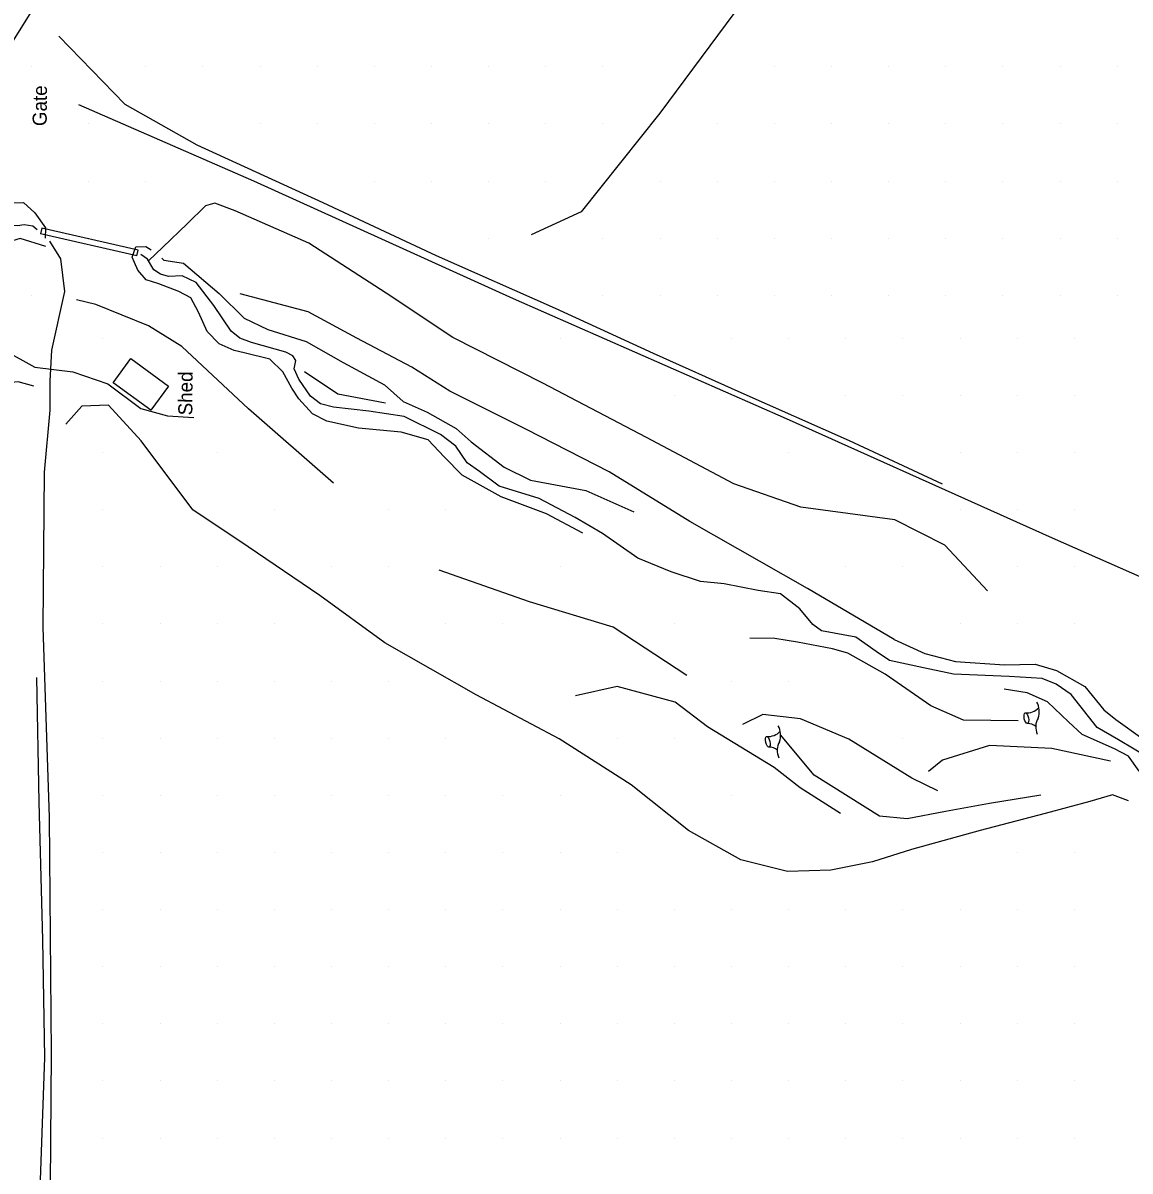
# Model space of a CAD drawing. Extents: x 19528164 to 19545171, y 7585743 to 7602745.
# Drawn here: x 19541782 to 19542169.5, y 7597363.5 to 7597765.3 of the extents above; entities that cross this region are included whole.
import ezdxf

# ---------------------------------------------------------------- set-up
doc = ezdxf.new("R2010")
doc.units = 0
for name, color, linetype in [('PhoBreakLine', 7, 'Continuous'), ('PhoBuilding', 7, 'Continuous'), ('PhoCulvert', 7, 'Continuous'), ('PhoDrainageArrow', 7, 'Continuous'), ('PhoEdgeBank', 7, 'Continuous'), ('PhoFence', 7, 'Continuous'), ('PhoISAEPoints', 7, 'Continuous'), ('PhoNotesDesign', 7, 'Continuous'), ('PhoSurveyLimits', 7, 'Continuous'), ('PhoVegetation', 7, 'Continuous'), ('SurBreakLine', 7, 'Continuous')]:
    doc.layers.add(name, color=color, linetype=linetype)

msp = doc.modelspace()

# ---------------------------------------------------------------- linework, layer by layer
at = {"layer": 'PhoBreakLine'}
for points in [[(19541794.59, 7597760.67), (19541817.6, 7597736.91), (19541842.87, 7597722.72), (19541886.98, 7597702.52), (19541926.62, 7597683.95), (19541968.3, 7597665.55), (19542002.51, 7597649.79), (19542033.25, 7597635.95), (19542071.12, 7597619.22), (19542103.72, 7597603.98)], [(19541790.02, 7597687.08), (19541780.99, 7597689.93), (19541776.86, 7597688.62), (19541769.15, 7597683.21), (19541763.12, 7597681.25), (19541759.23, 7597682.58), (19541754.77, 7597685.81), (19541752.34, 7597690.71), (19541751.47, 7597695.78), (19541752.59, 7597700.91), (19541755.01, 7597706.11), (19541760, 7597705.74), (19541764.14, 7597703), (19541768.36, 7597700.74), (19541772.19, 7597700.8), (19541776.62, 7597702.38), (19541782.18, 7597702.46), (19541786.15, 7597698.87), (19541789.93, 7597693.58), (19541789.8, 7597690.06)], [(19542086.97, 7597549.5), (19542056.56, 7597567.35), (19542015.43, 7597590.89), (19541987.17, 7597608.24), (19541958.19, 7597623.01), (19541931.45, 7597636.51), (19541918.06, 7597644.91), (19541898.85, 7597654.96), (19541881.8, 7597664.2), (19541857.97, 7597670.48)], [(19541890.62, 7597604.25), (19541860.98, 7597630.31), (19541837.64, 7597652.1), (19541825.87, 7597659.28), (19541807.51, 7597666.8), (19541800.71, 7597668.4)], [(19541732.47, 7597593.93), (19541736.31, 7597614.51), (19541743.61, 7597632.88), (19541753.02, 7597644.28), (19541765.27, 7597649.93), (19541775.46, 7597650.8), (19541786.14, 7597644.85), (19541799.39, 7597643.17), (19541811.74, 7597638.99), (19541823.27, 7597630.34), (19541832.56, 7597627.85), (19541841.75, 7597627.23)], [(19541908.91, 7597632.25), (19541892.23, 7597635.46), (19541880.47, 7597643.17)], [(19541785.75, 7597638.25), (19541780.28, 7597639.67), (19541774.31, 7597639.15), (19541767.22, 7597633.82), (19541757.4, 7597618.05), (19541747.81, 7597602.11), (19541740.55, 7597593.55)], [(19542168.95, 7597493.06), (19542163.36, 7597495.12), (19542155.37, 7597492.86), (19542139.81, 7597488.59), (19542117.05, 7597482.64), (19542093.01, 7597475.97), (19542079.31, 7597471.76), (19542064.71, 7597468.79), (19542049.62, 7597468.35), (19542033.3, 7597472.43), (19542014.9, 7597482.67), (19541994.89, 7597498.67), (19541969.63, 7597514.74), (19541940.6, 7597530.21), (19541908.59, 7597548.31), (19541885.9, 7597564.9), (19541860.76, 7597581.95), (19541841.47, 7597594.89), (19541823.35, 7597619.08), (19541811.95, 7597631.56), (19541802.6, 7597631.15), (19541797.04, 7597624.88)], [(19542014.38, 7597536.98), (19541988.52, 7597553.88), (19541959.32, 7597562.72), (19541927.63, 7597573.83)], [(19542130.36, 7597521.03), (19542111.24, 7597521.28), (19542099.75, 7597526.34), (19542083.79, 7597537.39), (19542070.67, 7597544.72), (19542065.29, 7597546.28), (19542053.09, 7597548.58), (19542045.1, 7597549.88), (19542036.42, 7597550.02)], [(19541822.57, 7597132.2), (19541810.92, 7597164.42), (19541800.98, 7597197.33), (19541794.34, 7597226.94), (19541790.27, 7597258.53), (19541788.36, 7597295.86), (19541787.4, 7597340.57), (19541789.66, 7597403.27), (19541788.92, 7597444.46), (19541787.69, 7597492.63), (19541786.84, 7597536.19)], [(19542068.16, 7597488.65), (19542054.04, 7597497.66), (19542044.86, 7597504.7), (19542021.63, 7597518.96), (19542010.24, 7597527.61), (19541989.99, 7597533.06), (19541975.38, 7597529.87)], [(19542102.24, 7597496.54), (19542093.14, 7597500.99), (19542071.08, 7597514.61), (19542054.14, 7597521.8), (19542040.98, 7597523.25), (19542033.86, 7597519.76)], [(19542138.24, 7597495.1), (19542120.3, 7597492.08), (19542104.84, 7597489.36), (19542091.52, 7597486.72), (19542081.84, 7597487.65), (19542058.88, 7597502.01), (19542047.19, 7597516.13)], [(19542162.65, 7597506.98), (19542142.1, 7597511.38), (19542120.31, 7597512.39), (19542103.83, 7597507.28), (19542098.98, 7597503.27)]]:
    msp.add_lwpolyline(points, dxfattribs=at)
at = {"layer": 'PhoBuilding'}
msp.add_lwpolyline([(19541819.7, 7597647.84), (19541832.87, 7597638.26), (19541826.69, 7597629.78), (19541813.53, 7597639.36)], close=True, dxfattribs=at)
at = {"layer": 'PhoCulvert'}
msp.add_line((19541821.83, 7597683.78), (19541788.18, 7597691.52), dxfattribs=at)
msp.add_lwpolyline([(19541821.83, 7597683.78), (19541822.29, 7597685.77), (19541788.64, 7597693.51), (19541788.18, 7597691.52)], dxfattribs=at)
at = {"layer": 'PhoDrainageArrow'}
for points in [[(19542214.51, 7598063.19), (19542207.4, 7598047.65), (19542193.16, 7598012.36), (19542173.5, 7597976.48), (19542154.96, 7597944.81), (19542128.53, 7597901.35), (19542106.27, 7597867.01), (19542085.79, 7597840.21), (19542059.07, 7597808.17), (19542033.85, 7597772.74), (19542004.95, 7597733.8), (19541977.35, 7597699.21), (19541959.81, 7597691.19)], [(19542119.64, 7597566.54), (19542104.65, 7597582.5), (19542087.15, 7597591.46), (19542054.24, 7597595.81), (19542030.81, 7597603.98), (19542000.21, 7597620.25), (19541963.94, 7597639.22), (19541932.42, 7597655.25), (19541909.14, 7597670.78), (19541882.07, 7597688.2), (19541856.29, 7597699.53), (19541849.2, 7597702.26), (19541845.89, 7597701.32), (19541839.51, 7597695.03), (19541830.94, 7597686.88), (19541825.92, 7597682.06)], [(19541786.97, 7597692.87), (19541785.45, 7597694.17), (19541782.36, 7597694.7), (19541780.12, 7597694.27), (19541773.6, 7597694.7), (19541768.16, 7597696.82), (19541764.12, 7597699.05), (19541756.53, 7597700.66)], [(19541827.48, 7597133.24), (19541816.17, 7597160.36), (19541805.14, 7597192.37), (19541797.66, 7597225.45), (19541792.88, 7597263.36), (19541791.07, 7597297.31), (19541791.46, 7597343.18), (19541792.01, 7597404.67), (19541791.29, 7597487.18), (19541789.09, 7597553.83), (19541789.58, 7597608.05), (19541791.51, 7597629.78), (19541791.45, 7597639.95), (19541792.08, 7597650.78), (19541796.67, 7597671.36), (19541795.22, 7597682.78), (19541791.39, 7597688.97)], [(19542176.39, 7597507.84), (19542165.38, 7597514.37), (19542158.01, 7597518.71), (19542148.82, 7597530.28), (19542143.62, 7597533.86), (19542138.7, 7597535.9), (19542127.12, 7597536.61), (19542107.7, 7597537.39), (19542097.19, 7597539.61), (19542085.32, 7597542.17), (19542080.65, 7597545.31), (19542073.53, 7597550.4), (19542061.49, 7597552.56), (19542058.5, 7597554.76), (19542053.89, 7597560.32), (19542047.17, 7597565.51), (19542039.32, 7597566.71), (19542027.4, 7597569), (19542019.12, 7597569.81), (19542008.9, 7597573.27), (19541997.21, 7597578.03), (19541984.8, 7597586.69), (19541975.26, 7597592.19), (19541962.62, 7597598.87), (19541948.65, 7597603.2), (19541941.75, 7597608.29), (19541937.48, 7597611.4), (19541933.53, 7597617.24), (19541928.1, 7597621.34), (19541915.38, 7597627.54), (19541903.07, 7597629.47), (19541890.64, 7597630.87), (19541886.09, 7597632.04), (19541882.61, 7597634.72), (19541878.57, 7597640.64), (19541876.89, 7597644.23), (19541877.55, 7597647.23), (19541876.42, 7597648.84), (19541874.03, 7597650.08), (19541861.96, 7597653.52), (19541857.85, 7597655.04), (19541854.82, 7597657.42), (19541848.84, 7597666.44), (19541842.64, 7597674.54), (19541837.68, 7597676.8), (19541832.98, 7597676.64), (19541830.1, 7597677.35), (19541827.75, 7597678.9), (19541825.58, 7597682.65), (19541823.27, 7597684.24)]]:
    msp.add_lwpolyline(points, dxfattribs=at)
at = {"layer": 'PhoEdgeBank'}
for points in [[(19541977.89, 7597586.77), (19541965.21, 7597593.54), (19541949.32, 7597599.47), (19541935.7, 7597607.1), (19541929.36, 7597613.44), (19541923.77, 7597619.43), (19541914.4, 7597622.15), (19541899.41, 7597623.47), (19541888.38, 7597625.95), (19541883.28, 7597628.52), (19541878.53, 7597633.82), (19541876.06, 7597637.53), (19541872.98, 7597643.25), (19541868.39, 7597647.71), (19541859.42, 7597649.91), (19541855.89, 7597650.66), (19541850.62, 7597653), (19541846.5, 7597657.3), (19541843.37, 7597664.12), (19541840.79, 7597669.1), (19541836.57, 7597671.37), (19541829.58, 7597674.08), (19541825.11, 7597675.47), (19541822.21, 7597678.77), (19541820.2, 7597683.41), (19541821.47, 7597686.95), (19541824.99, 7597687.13), (19541826.88, 7597685.93)], [(19541830.55, 7597683.04), (19541831.35, 7597682.34), (19541838.14, 7597681.29), (19541850.62, 7597670.69), (19541859.46, 7597662.06), (19541867.75, 7597658.09), (19541881.1, 7597653.8), (19541894.02, 7597646.5), (19541908.57, 7597638.7), (19541915.03, 7597632.86), (19541923.41, 7597629.15), (19541933.61, 7597623.44), (19541938.87, 7597618.77), (19541950.45, 7597609.87), (19541959.62, 7597605.34), (19541979, 7597601.66), (19541995.79, 7597594.25)], [(19542086.97, 7597549.5), (19542097.6, 7597544.59), (19542108.43, 7597541.84), (19542125.52, 7597540.68), (19542136.3, 7597540.93), (19542143.68, 7597538.7), (19542153.71, 7597533.04), (19542160.34, 7597524.86), (19542164.53, 7597521.53), (19542174, 7597514.72)], [(19542172.63, 7597503.39), (19542168.94, 7597508.7), (19542164.02, 7597511.27), (19542152.77, 7597516.3), (19542147.95, 7597520.72), (19542140.63, 7597527.7), (19542133.5, 7597530.85), (19542125.42, 7597532.1)]]:
    msp.add_lwpolyline(points, dxfattribs=at)
at = {"layer": 'PhoFence'}
msp.add_lwpolyline([(19542559.17, 7597397.99), (19542506.4, 7597422.3), (19542429.13, 7597458.02), (19542350.33, 7597492.61), (19542253.35, 7597536.04), (19542142.39, 7597585.04), (19542049.23, 7597626.77), (19541953.64, 7597668.77), (19541862.77, 7597709.96), (19541801.56, 7597736.62)], dxfattribs=at)
at = {"layer": 'PhoISAEPoints'}
for p, q in [((19541785, 7597750), (19541785, 7597750)), ((19541825, 7597750), (19541825, 7597750)), ((19541845, 7597750), (19541845, 7597750)), ((19541865, 7597750), (19541865, 7597750)), ((19541885, 7597750), (19541885, 7597750)), ((19541905, 7597750), (19541905, 7597750)), ((19541925, 7597750), (19541925, 7597750)), ((19541945, 7597750), (19541945, 7597750)), ((19541965, 7597750), (19541965, 7597750)), ((19541985, 7597750), (19541985, 7597750)), ((19542045, 7597750), (19542045, 7597750)), ((19542065, 7597750), (19542065, 7597750)), ((19542085, 7597750), (19542085, 7597750)), ((19542105, 7597750), (19542105, 7597750)), ((19542125, 7597750), (19542125, 7597750)), ((19542145, 7597750), (19542145, 7597750)), ((19542165, 7597750), (19542165, 7597750)), ((19541785, 7597730), (19541785, 7597730)), ((19541805, 7597730), (19541805, 7597730)), ((19541865, 7597730), (19541865, 7597730)), ((19541885, 7597730), (19541885, 7597730)), ((19541905, 7597730), (19541905, 7597730)), ((19541925, 7597730), (19541925, 7597730)), ((19541945, 7597730), (19541945, 7597730)), ((19541965, 7597730), (19541965, 7597730)), ((19541985, 7597730), (19541985, 7597730)), ((19542025, 7597730), (19542025, 7597730)), ((19542045, 7597730), (19542045, 7597730)), ((19542065, 7597730), (19542065, 7597730)), ((19542085, 7597730), (19542085, 7597730)), ((19542105, 7597730), (19542105, 7597730)), ((19542125, 7597730), (19542125, 7597730)), ((19542145, 7597730), (19542145, 7597730)), ((19542165, 7597730), (19542165, 7597730)), ((19541805, 7597710), (19541805, 7597710)), ((19541825, 7597710), (19541825, 7597710)), ((19541905, 7597710), (19541905, 7597710)), ((19541925, 7597710), (19541925, 7597710)), ((19541945, 7597710), (19541945, 7597710)), ((19541965, 7597710), (19541965, 7597710)), ((19542005, 7597710), (19542005, 7597710)), ((19542025, 7597710), (19542025, 7597710)), ((19542045, 7597710), (19542045, 7597710)), ((19542065, 7597710), (19542065, 7597710)), ((19542085, 7597710), (19542085, 7597710)), ((19542105, 7597710), (19542105, 7597710)), ((19542125, 7597710), (19542125, 7597710)), ((19542145, 7597710), (19542145, 7597710)), ((19542165, 7597710), (19542165, 7597710)), ((19541805, 7597690), (19541805, 7597690)), ((19541945, 7597690), (19541945, 7597690)), ((19541985, 7597690), (19541985, 7597690)), ((19542005, 7597690), (19542005, 7597690)), ((19542025, 7597690), (19542025, 7597690)), ((19542045, 7597690), (19542045, 7597690)), ((19542065, 7597690), (19542065, 7597690)), ((19542085, 7597690), (19542085, 7597690)), ((19542105, 7597690), (19542105, 7597690)), ((19542125, 7597690), (19542125, 7597690)), ((19542145, 7597690), (19542145, 7597690)), ((19542165, 7597690), (19542165, 7597690)), ((19541785, 7597670), (19541785, 7597670)), ((19541985, 7597670), (19541985, 7597670)), ((19542005, 7597670), (19542005, 7597670)), ((19542025, 7597670), (19542025, 7597670)), ((19542045, 7597670), (19542045, 7597670)), ((19542065, 7597670), (19542065, 7597670)), ((19542085, 7597670), (19542085, 7597670)), ((19542105, 7597670), (19542105, 7597670)), ((19542125, 7597670), (19542125, 7597670)), ((19542145, 7597670), (19542145, 7597670)), ((19542165, 7597670), (19542165, 7597670)), ((19541810, 7597655), (19541810, 7597655)), ((19541970, 7597655), (19541970, 7597655)), ((19542030, 7597655), (19542030, 7597655)), ((19542050, 7597655), (19542050, 7597655)), ((19542070, 7597655), (19542070, 7597655)), ((19542090, 7597655), (19542090, 7597655)), ((19542110, 7597655), (19542110, 7597655)), ((19542130, 7597655), (19542130, 7597655)), ((19542150, 7597655), (19542150, 7597655)), ((19542010, 7597635), (19542010, 7597635)), ((19542070, 7597635), (19542070, 7597635)), ((19542090, 7597635), (19542090, 7597635)), ((19542110, 7597635), (19542110, 7597635)), ((19542130, 7597635), (19542130, 7597635)), ((19542150, 7597635), (19542150, 7597635)), ((19541810, 7597615), (19541810, 7597615)), ((19541850, 7597615), (19541850, 7597615)), ((19542050, 7597615), (19542050, 7597615)), ((19542110, 7597615), (19542110, 7597615)), ((19542130, 7597615), (19542130, 7597615)), ((19542150, 7597615), (19542150, 7597615)), ((19541810, 7597595), (19541810, 7597595)), ((19541870, 7597595), (19541870, 7597595)), ((19541910, 7597595), (19541910, 7597595)), ((19541930, 7597595), (19541930, 7597595)), ((19542110, 7597595), (19542110, 7597595)), ((19542130, 7597595), (19542130, 7597595)), ((19542150, 7597595), (19542150, 7597595)), ((19541810, 7597575), (19541810, 7597575)), ((19541830, 7597575), (19541830, 7597575)), ((19541850, 7597575), (19541850, 7597575)), ((19541890, 7597575), (19541890, 7597575)), ((19541910, 7597575), (19541910, 7597575)), ((19541970, 7597575), (19541970, 7597575)), ((19542070, 7597575), (19542070, 7597575)), ((19542090, 7597575), (19542090, 7597575)), ((19542130, 7597575), (19542130, 7597575)), ((19542150, 7597575), (19542150, 7597575)), ((19541810, 7597555), (19541810, 7597555)), ((19541830, 7597555), (19541830, 7597555)), ((19541850, 7597555), (19541850, 7597555)), ((19541870, 7597555), (19541870, 7597555)), ((19541930, 7597555), (19541930, 7597555)), ((19541950, 7597555), (19541950, 7597555)), ((19542010, 7597555), (19542010, 7597555)), ((19542110, 7597555), (19542110, 7597555)), ((19542130, 7597555), (19542130, 7597555)), ((19542150, 7597555), (19542150, 7597555)), ((19541810, 7597535), (19541810, 7597535)), ((19541830, 7597535), (19541830, 7597535)), ((19541850, 7597535), (19541850, 7597535)), ((19541870, 7597535), (19541870, 7597535)), ((19541890, 7597535), (19541890, 7597535)), ((19541910, 7597535), (19541910, 7597535)), ((19542030, 7597535), (19542030, 7597535)), ((19542050, 7597535), (19542050, 7597535)), ((19541810, 7597515), (19541810, 7597515)), ((19541830, 7597515), (19541830, 7597515)), ((19541850, 7597515), (19541850, 7597515)), ((19541870, 7597515), (19541870, 7597515)), ((19541890, 7597515), (19541890, 7597515)), ((19541910, 7597515), (19541910, 7597515)), ((19541930, 7597515), (19541930, 7597515)), ((19541990, 7597515), (19541990, 7597515)), ((19542010, 7597515), (19542010, 7597515)), ((19542090, 7597515), (19542090, 7597515)), ((19541810, 7597495), (19541810, 7597495)), ((19541830, 7597495), (19541830, 7597495)), ((19541850, 7597495), (19541850, 7597495)), ((19541870, 7597495), (19541870, 7597495)), ((19541890, 7597495), (19541890, 7597495)), ((19541910, 7597495), (19541910, 7597495)), ((19541930, 7597495), (19541930, 7597495)), ((19541950, 7597495), (19541950, 7597495)), ((19541970, 7597495), (19541970, 7597495)), ((19542030, 7597495), (19542030, 7597495)), ((19541810, 7597475), (19541810, 7597475)), ((19541830, 7597475), (19541830, 7597475)), ((19541850, 7597475), (19541850, 7597475)), ((19541870, 7597475), (19541870, 7597475)), ((19541890, 7597475), (19541890, 7597475)), ((19541910, 7597475), (19541910, 7597475)), ((19541930, 7597475), (19541930, 7597475)), ((19541950, 7597475), (19541950, 7597475)), ((19541970, 7597475), (19541970, 7597475)), ((19541990, 7597475), (19541990, 7597475)), ((19542130, 7597475), (19542130, 7597475)), ((19542150, 7597475), (19542150, 7597475)), ((19541810, 7597455), (19541810, 7597455)), ((19541830, 7597455), (19541830, 7597455)), ((19541850, 7597455), (19541850, 7597455)), ((19541870, 7597455), (19541870, 7597455)), ((19541890, 7597455), (19541890, 7597455)), ((19541910, 7597455), (19541910, 7597455)), ((19541930, 7597455), (19541930, 7597455)), ((19541950, 7597455), (19541950, 7597455)), ((19541970, 7597455), (19541970, 7597455)), ((19541970, 7597455), (19541970, 7597455)), ((19541990, 7597455), (19541990, 7597455)), ((19542010, 7597455), (19542010, 7597455)), ((19542030, 7597455), (19542030, 7597455)), ((19542050, 7597455), (19542050, 7597455)), ((19542070, 7597455), (19542070, 7597455)), ((19542090, 7597455), (19542090, 7597455)), ((19542110, 7597455), (19542110, 7597455)), ((19542130, 7597455), (19542130, 7597455)), ((19542150, 7597455), (19542150, 7597455)), ((19541810, 7597435), (19541810, 7597435)), ((19541830, 7597435), (19541830, 7597435)), ((19541850, 7597435), (19541850, 7597435)), ((19541870, 7597435), (19541870, 7597435)), ((19541890, 7597435), (19541890, 7597435)), ((19541910, 7597435), (19541910, 7597435)), ((19541930, 7597435), (19541930, 7597435)), ((19541950, 7597435), (19541950, 7597435)), ((19541970, 7597435), (19541970, 7597435)), ((19541990, 7597435), (19541990, 7597435)), ((19542010, 7597435), (19542010, 7597435)), ((19542030, 7597435), (19542030, 7597435)), ((19542050, 7597435), (19542050, 7597435)), ((19542070, 7597435), (19542070, 7597435)), ((19542090, 7597435), (19542090, 7597435)), ((19542110, 7597435), (19542110, 7597435)), ((19542130, 7597435), (19542130, 7597435)), ((19542150, 7597435), (19542150, 7597435)), ((19541810, 7597415), (19541810, 7597415)), ((19541830, 7597415), (19541830, 7597415)), ((19541850, 7597415), (19541850, 7597415)), ((19541870, 7597415), (19541870, 7597415)), ((19541890, 7597415), (19541890, 7597415)), ((19541910, 7597415), (19541910, 7597415)), ((19541930, 7597415), (19541930, 7597415)), ((19541950, 7597415), (19541950, 7597415)), ((19541970, 7597415), (19541970, 7597415)), ((19541990, 7597415), (19541990, 7597415)), ((19542010, 7597415), (19542010, 7597415)), ((19542030, 7597415), (19542030, 7597415)), ((19542050, 7597415), (19542050, 7597415)), ((19542070, 7597415), (19542070, 7597415)), ((19542090, 7597415), (19542090, 7597415)), ((19542110, 7597415), (19542110, 7597415)), ((19542130, 7597415), (19542130, 7597415)), ((19542150, 7597415), (19542150, 7597415)), ((19541810, 7597395), (19541810, 7597395)), ((19541830, 7597395), (19541830, 7597395)), ((19541850, 7597395), (19541850, 7597395)), ((19541870, 7597395), (19541870, 7597395)), ((19541890, 7597395), (19541890, 7597395)), ((19541910, 7597395), (19541910, 7597395)), ((19541930, 7597395), (19541930, 7597395)), ((19541950, 7597395), (19541950, 7597395)), ((19541970, 7597395), (19541970, 7597395)), ((19541990, 7597395), (19541990, 7597395)), ((19542010, 7597395), (19542010, 7597395)), ((19542030, 7597395), (19542030, 7597395)), ((19542050, 7597395), (19542050, 7597395)), ((19542070, 7597395), (19542070, 7597395)), ((19542090, 7597395), (19542090, 7597395)), ((19542110, 7597395), (19542110, 7597395)), ((19542130, 7597395), (19542130, 7597395)), ((19542150, 7597395), (19542150, 7597395)), ((19541810, 7597375), (19541810, 7597375)), ((19541830, 7597375), (19541830, 7597375)), ((19541850, 7597375), (19541850, 7597375)), ((19541870, 7597375), (19541870, 7597375)), ((19541890, 7597375), (19541890, 7597375)), ((19541910, 7597375), (19541910, 7597375)), ((19541930, 7597375), (19541930, 7597375)), ((19541950, 7597375), (19541950, 7597375)), ((19541970, 7597375), (19541970, 7597375)), ((19541990, 7597375), (19541990, 7597375)), ((19542010, 7597375), (19542010, 7597375)), ((19542030, 7597375), (19542030, 7597375)), ((19542050, 7597375), (19542050, 7597375)), ((19542070, 7597375), (19542070, 7597375)), ((19542090, 7597375), (19542090, 7597375)), ((19542110, 7597375), (19542110, 7597375)), ((19542130, 7597375), (19542130, 7597375)), ((19542150, 7597375), (19542150, 7597375))]:
    msp.add_line(p, q, dxfattribs=at)
at = {"layer": 'PhoSurveyLimits'}
msp.add_lwpolyline([(19539053.39, 7595485.95), (19539048.98, 7595621.68), (19539215.71, 7595622.75), (19539469.49, 7595668.13), (19539712.52, 7595721.48), (19540033.03, 7595826.8), (19540393.26, 7595987.3), (19540770.63, 7595984.13), (19541136.8, 7596643.53), (19541624.4, 7597209.61), (19541649.44, 7597552.5), (19541832.46, 7597845.39), (19542376.97, 7598092.17)], dxfattribs=at)
at = {"layer": 'PhoVegetation'}
for centre, radius, start, end in [((19542133.18, 7597529.87), 6.05, 266.3123, 316.1038), ((19542130.35, 7597524.29), 7.33, 342.0289, 27.2686), ((19542142.57, 7597518.93), 6.1, 149.5086, 204.5326), ((19542042.68, 7597521.6), 6.05, 266.3123, 316.1038), ((19542039.85, 7597516.01), 7.33, 342.0289, 27.2686), ((19542133.79, 7597515.89), 4.21, 50.3183, 92.6588), ((19542052.08, 7597510.66), 6.1, 149.5086, 204.5326), ((19542043.29, 7597507.62), 4.21, 50.3183, 92.6588)]:
    msp.add_arc(centre, radius, start, end, dxfattribs=at)
for centre in [(19542133.19, 7597521.97), (19542042.69, 7597513.69)]:
    msp.add_ellipse(centre, major_axis=(0.4, -1.87), ratio=0.385758, dxfattribs=at)
at = {"layer": 'SurBreakLine'}
for points in [[(19542214.51, 7598063.19), (19542207.4, 7598047.65), (19542193.16, 7598012.36), (19542173.5, 7597976.48), (19542154.96, 7597944.81), (19542128.53, 7597901.35), (19542106.27, 7597867.01), (19542085.79, 7597840.21), (19542059.07, 7597808.17), (19542033.85, 7597772.74), (19542004.95, 7597733.8), (19541977.35, 7597699.21), (19541959.81, 7597691.19)], [(19542176.39, 7597507.84), (19542165.38, 7597514.37), (19542158.01, 7597518.71), (19542148.82, 7597530.28), (19542143.62, 7597533.86), (19542138.7, 7597535.9), (19542127.12, 7597536.61), (19542107.7, 7597537.39), (19542097.19, 7597539.61), (19542085.32, 7597542.17), (19542080.65, 7597545.31), (19542073.53, 7597550.4), (19542061.49, 7597552.56), (19542058.5, 7597554.76), (19542053.89, 7597560.32), (19542047.17, 7597565.51), (19542039.32, 7597566.71), (19542027.4, 7597569), (19542019.12, 7597569.81), (19542008.9, 7597573.27), (19541997.21, 7597578.03), (19541984.8, 7597586.69), (19541975.26, 7597592.19), (19541962.62, 7597598.87), (19541948.65, 7597603.2), (19541941.75, 7597608.29), (19541937.48, 7597611.4), (19541933.53, 7597617.24), (19541928.1, 7597621.34), (19541915.38, 7597627.54), (19541903.07, 7597629.47), (19541890.64, 7597630.87), (19541886.09, 7597632.04), (19541882.61, 7597634.72), (19541878.57, 7597640.64), (19541876.89, 7597644.23), (19541877.55, 7597647.23), (19541876.42, 7597648.84), (19541874.03, 7597650.08), (19541861.96, 7597653.52), (19541857.85, 7597655.04), (19541854.82, 7597657.42), (19541848.84, 7597666.44), (19541842.64, 7597674.54), (19541837.68, 7597676.8), (19541832.98, 7597676.64), (19541830.1, 7597677.35), (19541827.75, 7597678.9), (19541825.58, 7597682.65), (19541823.27, 7597684.24)]]:
    msp.add_lwpolyline(points, dxfattribs=at)

# ---------------------------------------------------------------- texts
at = {"layer": 'PhoNotesDesign'}
for s, p in [('Gate', (19541790.28, 7597729.22)), ('Shed', (19541841.26, 7597627.97))]:
    msp.add_text(s, height=4.92, rotation=89.5617, dxfattribs=at).set_placement(p)

doc.saveas('drawing.dxf')
